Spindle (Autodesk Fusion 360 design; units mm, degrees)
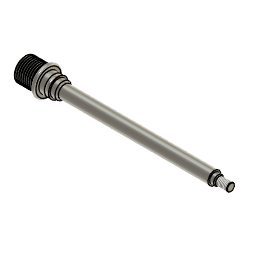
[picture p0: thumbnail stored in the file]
part number: 2025-12-16-14-32-34-761
sketch "Sketch1" plane through (0, 0, 0) normal (1, 0, 0) x axis (0, 1, 0)
  circle C1 centre (0, 0) radius 7.125
  point P1 (0, 0)
  point P2 (0, 0)
  coincident P1 P2
  dimension "d1" diameter C1 = 14.25
extrude "Extrude1" new body sketch "Sketch1" along normal blind 12
sketch "Sketch2" plane through (0, 0, 0) normal (0, 1, 0) x axis (1, 0, 0)
  line L1 (12, 7.125) -> (12, -7.125)
  line L2 (127, 0) -> (12, 0)
  line L3 (12, -9) -> (12, -7.125)
  line L4 (14.35, -9) -> (12, -9)
  line L5 (14.35, -6) -> (14.35, -9)
  line L6 (20.35, -6) -> (14.35, -6)
  line L7 (20.35, -5) -> (20.35, -6)
  line L8 (23.35, -5) -> (20.35, -5)
  line L9 (24.35, -4) -> (23.35, -5)
  line L10 (116.85, -4) -> (24.35, -4)
  line L11 (116.85, -3) -> (116.85, -4)
  line L12 (119.35, -3) -> (116.85, -3)
  line L13 (119.85, -2.5) -> (119.35, -3)
  line L14 (127, -2.5) -> (119.85, -2.5)
  line L15 (127, 0) -> (127, -2.5)
  line L16 (11, -7.125) -> (12, -7.125)
  line L17 (11, -6) -> (11, -7.125)
  line L18 (12, -6) -> (11, -6)
  line L19 (12, -7.125) -> (12, -6)
  point P4 (12, 0)
  point P2 (12, -7.125)
  point P6 (12, -7.125)
  point P19 (12, -7.125)
  point P5 (127, 0)
  point P7 (12, -9)
  point P8 (14.35, -9)
  point P9 (14.35, -6)
  point P10 (20.35, -6)
  point P11 (20.35, -5)
  point P12 (23.35, -5)
  point P15 (116.85, -3)
  point P16 (119.35, -3)
  point P21 (11, -6)
  point P22 (12, -6)
  midpoint L1 P4
  perpendicular L1 L2
  coincident P2 P6
  parallel L1 L3
  perpendicular L3 L4
  perpendicular L4 L5
  perpendicular L5 L6
  perpendicular L6 L7
  perpendicular L7 L8
  perpendicular L7 L10
  perpendicular L10 L11
  perpendicular L11 L12
  perpendicular L11 L14
  perpendicular L2 L15
  horizontal L16
  vertical L17
  horizontal L18
  vertical L19
  coincident P2 P19
  dimension "d4" distance P4 P5 = 115
  dimension "d5" = 18
  dimension "d6" = 12
  dimension "d7" = 10
  dimension "d8" distance P7 P8 = 2.35
  dimension "d9" distance P9 P10 = 6
  dimension "d10" distance P11 P12 = 3
  dimension "d11" = 8
  dimension "d12" distance P15 P16 = 2.5
  dimension "d13" = 6
  dimension "d14" = 5
  dimension "d15" distance L7 L11 = 96.5
  dimension "d16" angle L8 L9 = 45
  dimension "d17" angle L12 L13 = 45
  dimension "d18" = 12
  dimension "d19" distance P21 P22 = 1
revolve "Revolve1" sketch "Sketch2" AlongAngle 360
revolve "Revolve2" sketch "Sketch2" AlongAngle 360
chamfer "Chamfer1" distance 0.25
fillet "Fillet1"
thread "Thread1" ThreadOffset 0 ThreadLength 10
thread "Thread2" ThreadOffset 0 ThreadLength 10
sketch "Sketch3" plane through (0, 0, 0) normal (0, 1, 0) x axis (1, 0, 0)
  line L1 (20.35, -6) -> (14.35, -6)
  line L2 (127, 0) -> (12, 0)
  circle C1 centre (19.05, -6) radius 1.25
  point P3 (20.35, -6)
  point P4 (19.05, -6)
  dimension "d27" diameter C1 = 2.5
  dimension "d28" = 12
  dimension "d29" distance P3 P4 = 1.3
revolve "Revolve3" sketch "Sketch3" AlongAngle 360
